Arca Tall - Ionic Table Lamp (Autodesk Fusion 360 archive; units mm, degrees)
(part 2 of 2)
design "Balon v2"
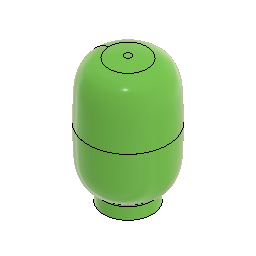
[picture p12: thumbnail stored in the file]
derived_base_feature "Derived Base Feature" bodies "Balon"
work_plane "WorkPlane1" AlongDistance 0
sketch "Sketch1" plane through (0, 0, 0) normal (0, 1, 0) x axis (1, 0, 0)
  line L1 (0, 317.5) -> (0, 2.9083)
  curve K1 (-82.9821, 124.2212) -> (-50.8, 237.8015)
  curve K2 (-51.0925, 237.681) -> (-50.8, 237.8015)
  curve K3 (-51.3855, 237.5558) -> (-51.0925, 237.681)
  curve K4 (-54.7608, 236.0513) -> (-51.3855, 237.5558)
  curve K5 (-57.9615, 234.05) -> (-54.7608, 236.0513)
  curve K6 (-67.2727, 226.749) -> (-57.9615, 234.05)
  curve K7 (-69.0552, 224.2615) -> (-67.2727, 226.749)
  curve K8 (-72.1872, 218.7832) -> (-69.0552, 224.2615)
  curve K9 (-74.1213, 215.1556) -> (-72.1872, 218.7832)
  curve K10 (-78.3031, 204.3965) -> (-74.1213, 215.1556)
  curve K11 (-79.7275, 197.3397) -> (-78.3031, 204.3965)
  curve K12 (-81.3333, 185.4664) -> (-79.7275, 197.3397)
  curve K13 (-81.6254, 178.4008) -> (-81.3333, 185.4664)
  curve K14 (-82.49, 152.2133) -> (-81.6254, 178.4008)
  curve K15 (-82.9821, 136.067) -> (-82.49, 152.2133)
  curve K16 (-82.9821, 124.2212) -> (-82.9821, 136.067)
  curve K17 (50.8, 237.7999) -> (82.9821, 124.2212)
  curve K18 (82.9821, 140.3031) -> (82.9821, 124.2212)
  curve K19 (81.9353, 169.4257) -> (82.9821, 140.3031)
  curve K20 (81.3621, 183.6489) -> (81.9353, 169.4257)
  curve K21 (80.9478, 189.8724) -> (81.3621, 183.6489)
  curve K22 (77.8147, 206.9858) -> (80.9478, 189.8724)
  curve K23 (74.9652, 213.2153) -> (77.8147, 206.9858)
  curve K24 (69.4688, 224.1531) -> (74.9652, 213.2153)
  curve K25 (67.2512, 226.458) -> (69.4688, 224.1531)
  curve K26 (61.5696, 231.3138) -> (67.2512, 226.458)
  curve K27 (57.377, 234.6711) -> (61.5696, 231.3138)
  curve K28 (52.0556, 237.2628) -> (57.377, 234.6711)
  curve K29 (51.4313, 237.5413) -> (52.0556, 237.2628)
  curve K30 (50.8, 237.7999) -> (51.4313, 237.5413)
  line L2 (-50.8, 317.5) -> (-50.8, 237.8015)
  line L3 (50.8, 317.5) -> (50.8, 237.7999)
  line L4 (-19.0713, 6.7501) -> (-19.0713, 6.7501)
  curve K31 (82.9821, 124.1958) -> (40.1509, 7.3012)
  curve K32 (41.8198, 7.6176) -> (40.1509, 7.3012)
  curve K33 (43.2113, 8.0663) -> (41.8198, 7.6176)
  curve K34 (47.0139, 9.2854) -> (43.2113, 8.0663)
  curve K35 (47.3314, 9.3805) -> (47.0139, 9.2854)
  curve K36 (50.1192, 10.3272) -> (47.3314, 9.3805)
  curve K37 (51.833, 11.0085) -> (50.1192, 10.3272)
  curve K38 (57.8313, 14.1895) -> (51.833, 11.0085)
  curve K39 (61.4491, 17.0488) -> (57.8313, 14.1895)
  curve K40 (66.8203, 21.5867) -> (61.4491, 17.0488)
  curve K41 (68.5372, 23.5528) -> (66.8203, 21.5867)
  curve K42 (71.2201, 27.8971) -> (68.5372, 23.5528)
  curve K43 (74.7424, 33.8984) -> (71.2201, 27.8971)
  curve K44 (78.2342, 44.8406) -> (74.7424, 33.8984)
  curve K45 (79.6792, 50.3463) -> (78.2342, 44.8406)
  curve K46 (81.3558, 63.5576) -> (79.6792, 50.3463)
  curve K47 (81.6386, 70.4415) -> (81.3558, 63.5576)
  curve K48 (82.4897, 96.2198) -> (81.6386, 70.4415)
  curve K49 (82.9814, 112.3523) -> (82.4897, 96.2198)
  curve K50 (82.9821, 124.1958) -> (82.9814, 112.3523)
  curve K51 (-40.1501, 7.301) -> (-82.9821, 124.1958)
  curve K52 (-82.9813, 110.5256) -> (-82.9821, 124.1958)
  curve K53 (-82.2545, 88.8594) -> (-82.9813, 110.5256)
  curve K54 (-81.6277, 70.519) -> (-82.2545, 88.8594)
  curve K55 (-81.3572, 64.3441) -> (-81.6277, 70.519)
  curve K56 (-79.4149, 46.8924) -> (-81.3572, 64.3441)
  curve K57 (-76.5204, 38.9768) -> (-79.4149, 46.8924)
  curve K58 (-73.5142, 32.2947) -> (-76.5204, 38.9768)
  curve K59 (-72.5556, 30.3818) -> (-73.5142, 32.2947)
  curve K60 (-69.7914, 25.3691) -> (-72.5556, 30.3818)
  curve K61 (-68.3824, 23.4028) -> (-69.7914, 25.3691)
  curve K62 (-64.5419, 19.5456) -> (-68.3824, 23.4028)
  curve K63 (-62.3002, 17.7646) -> (-64.5419, 19.5456)
  curve K64 (-53.6583, 11.1976) -> (-62.3002, 17.7646)
  curve K65 (-49.6968, 10.1396) -> (-53.6583, 11.1976)
  curve K66 (-43.4141, 8.1331) -> (-49.6968, 10.1396)
  curve K67 (-41.9704, 7.6516) -> (-43.4141, 8.1331)
  curve K68 (-40.1963, 7.3098) -> (-41.9704, 7.6516)
  curve K69 (-40.1732, 7.3054) -> (-40.1963, 7.3098)
  curve K70 (-40.1501, 7.301) -> (-40.1732, 7.3054)
  line L5 (-82.9821, 124.1958) -> (-82.9821, 124.2212)
  line L6 (82.9821, 124.2212) -> (82.9821, 124.1958)
  line L7 (0, 317.5) -> (-50.8, 317.5)
  line L8 (7.2015, 3.048) -> (0, 3.048)
  line L9 (0, 3.048) -> (-7.2015, 3.048)
  arc A1 centre (0, 188.595) radius 185.6867 clockwise from (-7.2015, 3.048) to (-40.1502, 7.301)
  arc A2 centre (0, 188.595) radius 185.6867 clockwise from (40.151, 7.3012) to (7.2015, 3.048)
  point P38 (-40.1502, 7.301)
  point P43 (40.1509, 7.3012)
  point P62 (-40.1501, 7.301)
  point P81 (40.151, 7.3012)
  point P84 (0, 3.048)
  vertical L1
  horizontal L4
  coincident P38 K51
  symmetric L1 A1 A2
  coincident A2 P43
  coincident A1 P62
  coincident K31 P81
  perpendicular L2 L7
  horizontal L8
  coincident L1 P84
  horizontal L9
revolve "Revolve1" sketch "Sketch1" AlongAngle 360
shell "Shell1" innerThickness 3.81
fillet "Fillet1" radius 6.35
offset_faces "OffsetFaces1" distance -50.8
move "Move1"
move "Move2"
component_from_bodies "Body->Comp1"
component_from_bodies "Body->Comp2"
sketch "Sketch2" plane through (0, 0, 0) normal (0, 1, 0) x axis (1, 0, 0)
  line L1 (-85.5221, 124.2212) -> (-85.5221, 124.1961)
  curve K1 (-58.9057, 236.4383) -> (-50.8, 241.7989)
  curve K2 (-50.8, 241.554) -> (-50.8, 241.7989)
  curve K3 (-50.904, 240.933) -> (-50.8, 241.554)
  curve K4 (-51.2936, 240.2837) -> (-50.904, 240.933)
  curve K5 (-51.734, 239.7561) -> (-51.2936, 240.2837)
  curve K6 (-53.328, 238.5038) -> (-51.734, 239.7561)
  curve K7 (-54.0892, 238.1997) -> (-53.328, 238.5038)
  curve K8 (-58.9057, 236.4383) -> (-54.0892, 238.1997)
  curve K9 (-89.3309, 124.2212) -> (-58.9057, 236.4383)
  curve K10 (-62.6336, 234.9735) -> (-58.9057, 236.4383)
  curve K11 (-65.581, 233.1032) -> (-62.6336, 234.9735)
  curve K12 (-73.0224, 227.0019) -> (-65.581, 233.1032)
  curve K13 (-74.8981, 224.836) -> (-73.0224, 227.0019)
  curve K14 (-78.1104, 219.6097) -> (-74.8981, 224.836)
  curve K15 (-80.2663, 215.561) -> (-78.1104, 219.6097)
  curve K16 (-84.0943, 205.8277) -> (-80.2663, 215.561)
  curve K17 (-85.4655, 200.1154) -> (-84.0943, 205.8277)
  curve K18 (-87.4092, 188.5789) -> (-85.4655, 200.1154)
  curve K19 (-87.7349, 182.3889) -> (-87.4092, 188.5789)
  curve K20 (-88.4233, 165.9645) -> (-87.7349, 182.3889)
  curve K21 (-89.328, 138.6964) -> (-88.4233, 165.9645)
  curve K22 (-89.3309, 124.2212) -> (-89.328, 138.6964)
  line L2 (-89.3309, 124.1958) -> (-89.3309, 124.2212)
  curve K23 (-46.5001, 7.301) -> (-89.3309, 124.1958)
  curve K24 (-89.3314, 112.4293) -> (-89.3309, 124.1958)
  curve K25 (-88.8181, 95.3068) -> (-89.3314, 112.4293)
  curve K26 (-88.346, 81.2892) -> (-88.8181, 95.3068)
  curve K27 (-88.0298, 70.4902) -> (-88.346, 81.2892)
  curve K28 (-87.1514, 58.328) -> (-88.0298, 70.4902)
  curve K29 (-86.3326, 50.6119) -> (-87.1514, 58.328)
  curve K30 (-81.0932, 33.6688) -> (-86.3326, 50.6119)
  curve K31 (-77.3163, 27.4309) -> (-81.0932, 33.6688)
  curve K32 (-74.8955, 23.6666) -> (-77.3163, 27.4309)
  curve K33 (-73.5108, 22.0741) -> (-74.8955, 23.6666)
  curve K34 (-70.2346, 19.0457) -> (-73.5108, 22.0741)
  curve K35 (-64.8094, 14.3548) -> (-70.2346, 19.0457)
  curve K36 (-56.6696, 10.3041) -> (-64.8094, 14.3548)
  curve K37 (-54.0053, 9.483) -> (-56.6696, 10.3041)
  curve K38 (-49.1487, 7.9411) -> (-54.0053, 9.483)
  curve K39 (-48.3482, 7.6526) -> (-49.1487, 7.9411)
  curve K40 (-46.5001, 7.301) -> (-48.3482, 7.6526)
  line L3 (0, 266.7) -> (0, 0)
  line L4 (0, 3.048) -> (-7.7894, 3.048)
  line L5 (-50.8, 266.7) -> (-50.8, 241.7989)
  line L6 (0, 266.7) -> (-50.8, 266.7)
  arc A1 centre (-6.9779, 188.7329) radius 185.6867 clockwise from (-7.7894, 3.048) to (-46.5001, 7.301)
  point P1 (0, 0)
  point P44 (0, 0)
  point P46 (0, 3.048)
  point P5 (-50.8, 241.554)
  point P49 (0, 266.7)
  coincident P1 P44
  coincident L3 P46
  coincident P5 L5
  coincident L3 P49
revolve "Revolve2" sketch "Sketch2" AlongAngle 360 bodies "Balon v3"
shell "Shell2" innerThickness 3.81
component_from_bodies "Body->Comp3"
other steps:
base_feature "Base Feature1" bodies "Balon"
base_feature "Base Feature1" bodies "Balon v3"
base_feature "Base Feature1" bodies "Balon v2"
create_component "CreateComponent1"
remove_body "RemoveBody1"
create_component "CreateComponent2"
remove_body "RemoveBody2"
create_component "CreateComponent3"
remove_body "RemoveBody3"
named bodies: "Balon", "Balon v2", "Balon v3"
